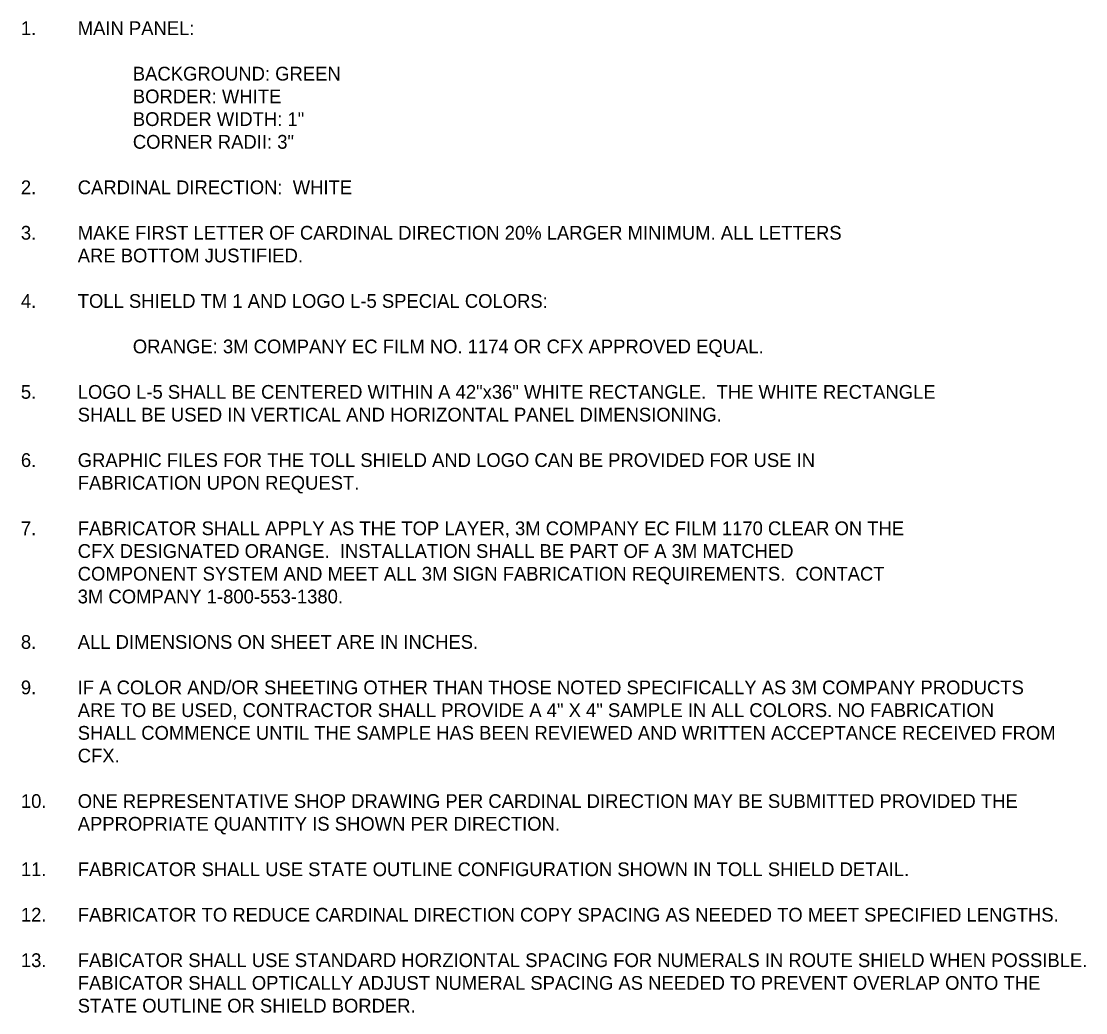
# Model space of a CAD drawing. Extents: x 51788 to 52424, y 9835 to 10249.
# Drawn here: x 52148.8 to 52365.1, y 10047.8 to 10249.3 of the extents above; entities that cross this region are included whole.
import ezdxf

# ---------------------------------------------------------------- set-up
doc = ezdxf.new("R2010")
doc.units = 0
doc.layers.add('TextNotes', color=7, linetype='Continuous')

msp = doc.modelspace()

# ---------------------------------------------------------------- texts
at = {"layer": 'TextNotes'}
for s, p in [('1.', (52148.75, 10246.52)), ('MAIN PANEL:', (52160.3, 10246.52)), ('BACKGROUND: GREEN', (52171.5, 10237.28)), ('BORDER: WHITE', (52171.5, 10232.66)), ('BORDER WIDTH: 1"', (52171.5, 10228.04)), ('CORNER RADII: 3"', (52171.5, 10223.42)), ('2.', (52148.75, 10214.18)), ('CARDINAL DIRECTION:  WHITE', (52160.3, 10214.18)), ('3.', (52148.75, 10204.94)), ('MAKE FIRST LETTER OF CARDINAL DIRECTION 20% LARGER MINIMUM. ALL LETTERS', (52160.3, 10204.94)), ('ARE BOTTOM JUSTIFIED.', (52160.3, 10200.32)), ('4.', (52148.75, 10191.08)), ('TOLL SHIELD TM 1 AND LOGO L-5 SPECIAL COLORS:', (52160.3, 10191.08)), ('ORANGE: 3M COMPANY EC FILM NO. 1174 OR CFX APPROVED EQUAL.', (52171.5, 10181.84)), ('5.', (52148.75, 10172.6)), ('LOGO L-5 SHALL BE CENTERED WITHIN A 42"x36" WHITE RECTANGLE.  THE WHITE RECTANGLE', (52160.3, 10172.6)), ('SHALL BE USED IN VERTICAL AND HORIZONTAL PANEL DIMENSIONING.', (52160.3, 10167.98)), ('6.', (52148.75, 10158.74)), ('GRAPHIC FILES FOR THE TOLL SHIELD AND LOGO CAN BE PROVIDED FOR USE IN', (52160.3, 10158.74)), ('FABRICATION UPON REQUEST.', (52160.3, 10154.12)), ('7.', (52148.75, 10144.88)), ('FABRICATOR SHALL APPLY AS THE TOP LAYER, 3M COMPANY EC FILM 1170 CLEAR ON THE', (52160.3, 10144.88)), ('CFX DESIGNATED ORANGE.  INSTALLATION SHALL BE PART OF A 3M MATCHED', (52160.3, 10140.26)), ('COMPONENT SYSTEM AND MEET ALL 3M SIGN FABRICATION REQUIREMENTS.  CONTACT', (52160.3, 10135.64)), ('3M COMPANY 1-800-553-1380.', (52160.3, 10131.02)), ('8.', (52148.75, 10121.78)), ('ALL DIMENSIONS ON SHEET ARE IN INCHES.', (52160.3, 10121.78)), ('9.', (52148.75, 10112.54)), ('IF A COLOR AND/OR SHEETING OTHER THAN THOSE NOTED SPECIFICALLY AS 3M COMPANY PRODUCTS', (52160.3, 10112.54)), ('ARE TO BE USED, CONTRACTOR SHALL PROVIDE A 4" X 4" SAMPLE IN ALL COLORS. NO FABRICATION', (52160.3, 10107.92)), ('SHALL COMMENCE UNTIL THE SAMPLE HAS BEEN REVIEWED AND WRITTEN ACCEPTANCE RECEIVED FROM ', (52160.3, 10103.3)), ('CFX.', (52160.3, 10098.68)), ('10.', (52148.75, 10089.44)), ('ONE REPRESENTATIVE SHOP DRAWING PER CARDINAL DIRECTION MAY BE SUBMITTED PROVIDED THE', (52160.3, 10089.44)), ('APPROPRIATE QUANTITY IS SHOWN PER DIRECTION.', (52160.3, 10084.82)), ('11.', (52148.75, 10075.58)), ('FABRICATOR SHALL USE STATE OUTLINE CONFIGURATION SHOWN IN TOLL SHIELD DETAIL.', (52160.3, 10075.58)), ('12.', (52148.75, 10066.34)), ('FABRICATOR TO REDUCE CARDINAL DIRECTION COPY SPACING AS NEEDED TO MEET SPECIFIED LENGTHS.', (52160.3, 10066.34)), ('13.', (52148.75, 10057.1)), ('FABICATOR SHALL USE STANDARD HORZIONTAL SPACING FOR NUMERALS IN ROUTE SHIELD WHEN POSSIBLE.', (52160.3, 10057.1)), ('FABICATOR SHALL OPTICALLY ADJUST NUMERAL SPACING AS NEEDED TO PREVENT OVERLAP ONTO THE', (52160.3, 10052.48)), ('STATE OUTLINE OR SHIELD BORDER.', (52160.3, 10047.86))]:
    msp.add_text(s, height=2.8, dxfattribs=at).set_placement(p)

doc.saveas('drawing.dxf')
